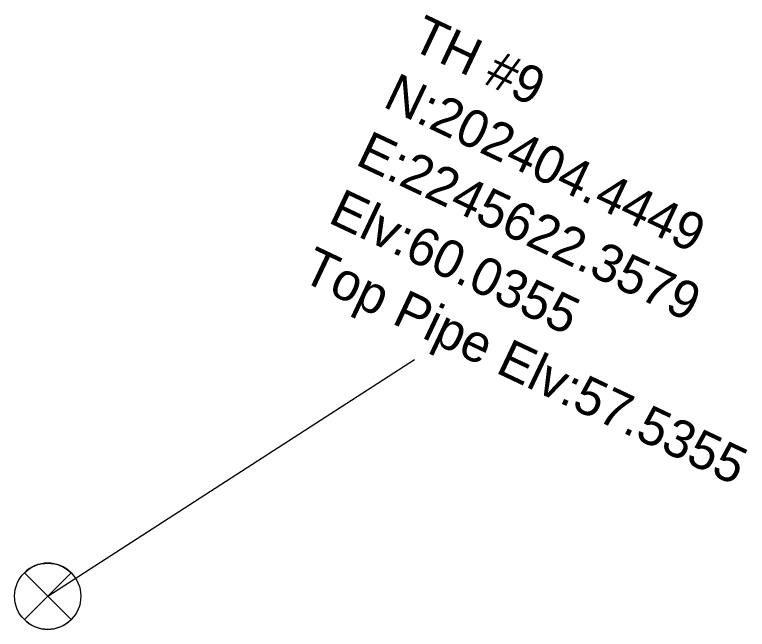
# Model space of a CAD drawing. Extents: x 2245619.3 to 2245687.4, y 202401.4 to 202458.5.
import ezdxf

# ---------------------------------------------------------------- set-up
doc = ezdxf.new("R2010")
doc.units = 0
for name, color, linetype in [('Exist Utilities Sanitary Sewer Test Hole SUE LOS A CELL', 7, 'Continuous'), ('Exist Utilities Sanitary Sewer Test Hole SUE LOS A Leader', 7, 'Continuous'), ('Exist Utilities Sanitary Sewer Test Hole SUE LOS A Text', 7, 'Continuous')]:
    doc.layers.add(name, color=color, linetype=linetype)

msp = doc.modelspace()

# ---------------------------------------------------------------- linework, layer by layer
at = {"layer": 'Exist Utilities Sanitary Sewer Test Hole SUE LOS A CELL'}
for points in [[(2245624.532, 202406.619), (2245620.184, 202402.271), (2245622.358, 202404.445), (2245620.184, 202406.619), (2245624.532, 202402.271)], [(2245620.184, 202406.619), (2245622.358, 202404.445), (2245624.532, 202406.619)], [(2245624.532, 202402.271), (2245622.358, 202404.445), (2245620.184, 202402.271)]]:
    msp.add_lwpolyline(points, dxfattribs=at)
msp.add_circle((2245622.358, 202404.445), 3.074, dxfattribs=at)
for start, end in [(45, 135), (225, 315)]:
    msp.add_arc((2245622.358, 202404.445), 3.074, start, end, dxfattribs=at)
at = {"layer": 'Exist Utilities Sanitary Sewer Test Hole SUE LOS A Leader'}
msp.add_line((2245622.358, 202404.445), (2245656.436, 202426.454), dxfattribs=at)

# ---------------------------------------------------------------- texts
at = {"layer": 'Exist Utilities Sanitary Sewer Test Hole SUE LOS A Text'}
for s, p in [('TH #9', (2245655.925, 202455.358)), ('N:202404.4449', (2245653.381, 202449.979)), ('E:2245622.3579', (2245650.837, 202444.6)), ('Elv:60.0355', (2245648.292, 202439.222)), ('Top Pipe Elv:57.5355', (2245645.748, 202433.843))]:
    msp.add_text(s, height=3.5, rotation=334.68484, dxfattribs=at).set_placement(p)

doc.saveas('drawing.dxf')
